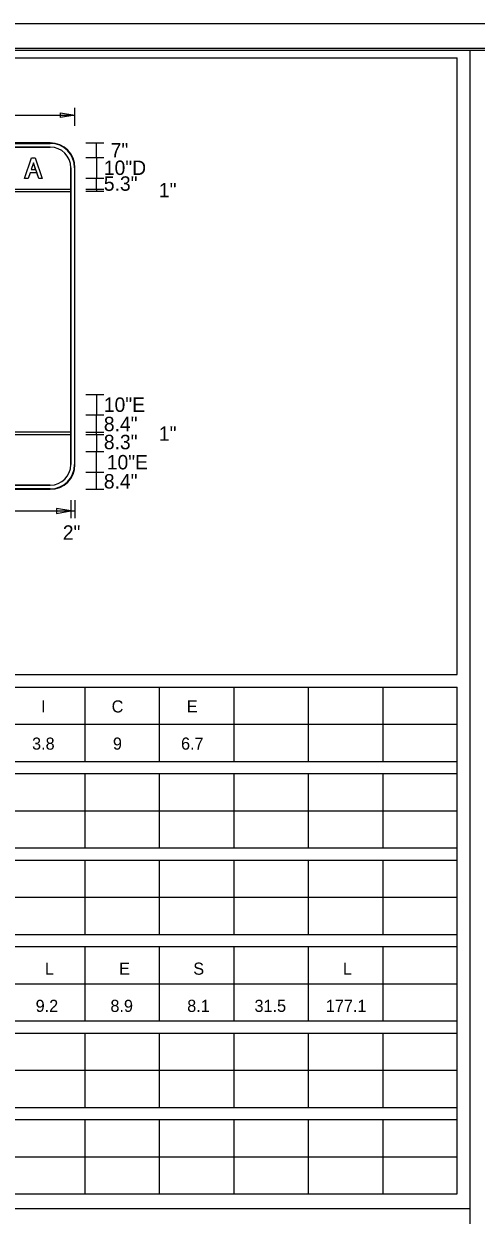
# Model space of a CAD drawing. Extents: x 17890071 to 17890754, y 17897628 to 17897992.
# Drawn here: x 17890133.85 to 17890152.13, y 17897822.34 to 17897870.5 of the extents above; entities that cross this region are included whole.
import ezdxf

# ---------------------------------------------------------------- set-up
doc = ezdxf.new("R2010")
doc.units = 0
for name, color, linetype in [('GSBWFill', 7, 'Continuous'), ('GSColorFill', 7, 'Continuous'), ('GSDims', 7, 'Continuous'), ('GSOutline', 7, 'Continuous'), ('GSSign', 7, 'Continuous'), ('PlotBorder_dp', 7, 'Continuous'), ('SheetBorder_dp', 7, 'Continuous'), ('SheetLinesMisc2_dp', 7, 'Continuous')]:
    doc.layers.add(name, color=color, linetype=linetype)

msp = doc.modelspace()

# ---------------------------------------------------------------- linework, layer by layer
at = {"layer": 'GSBWFill'}
for p, q in [((17890134.913, 17897865.68), (17890116.913, 17897865.68)), ((17890116.913, 17897865.514), (17890134.913, 17897865.514)), ((17890135.747, 17897864.68), (17890135.747, 17897852.68)), ((17890135.913, 17897852.68), (17890135.913, 17897864.68)), ((17890135.747, 17897863.798), (17890116.08, 17897863.798)), ((17890116.08, 17897863.715), (17890135.747, 17897863.715)), ((17890135.747, 17897863.715), (17890135.747, 17897863.798)), ((17890135.747, 17897853.984), (17890116.08, 17897853.984)), ((17890116.08, 17897853.901), (17890135.747, 17897853.901)), ((17890135.747, 17897853.901), (17890135.747, 17897853.984)), ((17890134.913, 17897851.847), (17890116.915, 17897851.847)), ((17890116.915, 17897851.68), (17890134.913, 17897851.68))]:
    msp.add_line(p, q, dxfattribs=at)
msp.add_lwpolyline([(17890133.88, 17897864.246), (17890134.163, 17897865.079), (17890134.305, 17897865.079), (17890134.588, 17897864.246), (17890134.447, 17897864.246), (17890134.234, 17897864.873), (17890134.144, 17897864.608), (17890134.324, 17897864.608), (17890134.369, 17897864.475), (17890134.099, 17897864.475), (17890134.021, 17897864.246)], close=True, dxfattribs=at)
for centre, radius, start, end in [((17890134.913, 17897864.68), 1, 0, 90), ((17890134.913, 17897864.68), 0.833, 0, 90), ((17890134.913, 17897852.68), 1, 270, 0), ((17890134.913, 17897852.68), 0.833, 270, 0)]:
    msp.add_arc(centre, radius, start, end, dxfattribs=at)
at = {"layer": 'GSColorFill'}
for p, q in [((17890134.913, 17897865.68), (17890116.913, 17897865.68)), ((17890134.913, 17897865.68), (17890116.913, 17897865.68)), ((17890134.913, 17897865.68), (17890116.913, 17897865.68)), ((17890116.913, 17897865.664), (17890134.913, 17897865.664)), ((17890116.913, 17897865.514), (17890134.913, 17897865.514)), ((17890135.747, 17897864.68), (17890135.747, 17897852.68)), ((17890135.897, 17897864.68), (17890135.897, 17897852.68)), ((17890135.913, 17897852.68), (17890135.913, 17897864.68)), ((17890135.913, 17897852.68), (17890135.913, 17897864.68)), ((17890135.913, 17897852.68), (17890135.913, 17897864.68)), ((17890135.747, 17897863.798), (17890116.08, 17897863.798)), ((17890116.08, 17897863.715), (17890135.747, 17897863.715)), ((17890135.747, 17897863.715), (17890135.747, 17897863.798)), ((17890135.747, 17897853.984), (17890116.08, 17897853.984)), ((17890116.08, 17897853.901), (17890135.747, 17897853.901)), ((17890135.747, 17897853.901), (17890135.747, 17897853.984)), ((17890134.913, 17897851.697), (17890116.913, 17897851.697)), ((17890116.913, 17897851.68), (17890134.913, 17897851.68)), ((17890116.913, 17897851.68), (17890134.913, 17897851.68)), ((17890134.913, 17897851.847), (17890116.915, 17897851.847)), ((17890116.915, 17897851.68), (17890134.913, 17897851.68))]:
    msp.add_line(p, q, dxfattribs=at)
msp.add_lwpolyline([(17890133.88, 17897864.246), (17890134.163, 17897865.079), (17890134.305, 17897865.079), (17890134.588, 17897864.246), (17890134.447, 17897864.246), (17890134.234, 17897864.873), (17890134.144, 17897864.608), (17890134.324, 17897864.608), (17890134.369, 17897864.475), (17890134.099, 17897864.475), (17890134.021, 17897864.246)], close=True, dxfattribs=at)
for centre, radius, start, end in [((17890134.913, 17897864.68), 1, 0, 90), ((17890134.913, 17897864.68), 1, 0, 90), ((17890134.913, 17897864.68), 1, 0, 90), ((17890134.913, 17897864.68), 0.983, 0, 90), ((17890134.913, 17897864.68), 0.833, 0, 90), ((17890134.913, 17897852.68), 1, 270, 0), ((17890134.913, 17897852.68), 1, 270, 0), ((17890134.913, 17897852.68), 0.833, 270, 0), ((17890134.913, 17897852.68), 1, 270, 0), ((17890134.913, 17897852.68), 0.983, 270, 0)]:
    msp.add_arc(centre, radius, start, end, dxfattribs=at)
at = {"layer": 'GSDims'}
for p, q in [((17890135.913, 17897866.368), (17890135.913, 17897867.097)), ((17890115.913, 17897866.806), (17890135.913, 17897866.806)), ((17890136.351, 17897865.68), (17890137.08, 17897865.68)), ((17890136.788, 17897865.094), (17890136.788, 17897865.68)), ((17890136.351, 17897865.094), (17890137.08, 17897865.094)), ((17890136.351, 17897865.094), (17890137.08, 17897865.094)), ((17890136.788, 17897865.094), (17890136.788, 17897864.26)), ((17890136.351, 17897864.26), (17890137.08, 17897864.26)), ((17890136.351, 17897864.26), (17890137.08, 17897864.26)), ((17890136.788, 17897863.815), (17890136.788, 17897864.26)), ((17890136.351, 17897863.815), (17890137.08, 17897863.815)), ((17890136.351, 17897863.815), (17890137.08, 17897863.815)), ((17890136.351, 17897863.732), (17890137.08, 17897863.732)), ((17890136.351, 17897863.732), (17890137.08, 17897863.732)), ((17890136.788, 17897863.815), (17890136.788, 17897863.732)), ((17890136.351, 17897855.517), (17890137.08, 17897855.517)), ((17890136.351, 17897855.517), (17890137.08, 17897855.517)), ((17890136.788, 17897855.517), (17890136.788, 17897854.684)), ((17890136.351, 17897854.684), (17890137.08, 17897854.684)), ((17890136.351, 17897854.684), (17890137.08, 17897854.684)), ((17890136.788, 17897853.984), (17890136.788, 17897854.684)), ((17890136.351, 17897853.984), (17890137.08, 17897853.984)), ((17890136.351, 17897853.984), (17890137.08, 17897853.984)), ((17890136.351, 17897853.9), (17890137.08, 17897853.9)), ((17890136.351, 17897853.9), (17890137.08, 17897853.9)), ((17890136.788, 17897853.9), (17890136.788, 17897853.984)), ((17890136.788, 17897853.9), (17890136.788, 17897853.213)), ((17890136.351, 17897853.213), (17890137.08, 17897853.213)), ((17890136.788, 17897852.379), (17890136.788, 17897853.213)), ((17890136.351, 17897852.379), (17890137.08, 17897852.379)), ((17890136.788, 17897851.68), (17890136.788, 17897852.379)), ((17890136.351, 17897851.68), (17890137.08, 17897851.68)), ((17890135.747, 17897851.243), (17890135.747, 17897850.514)), ((17890135.747, 17897851.243), (17890135.747, 17897850.514)), ((17890135.913, 17897851.243), (17890135.913, 17897850.514)), ((17890116.08, 17897850.805), (17890135.747, 17897850.805)), ((17890135.747, 17897850.805), (17890135.913, 17897850.805))]:
    msp.add_line(p, q, dxfattribs=at)
for points in [[(17890135.913, 17897866.806), (17890135.33, 17897866.708), (17890135.33, 17897866.903)], [(17890135.747, 17897850.805), (17890135.163, 17897850.903), (17890135.163, 17897850.708)]]:
    msp.add_lwpolyline(points, close=True, dxfattribs=at)
at = {"layer": 'GSOutline'}
for p, q in [((17890134.913, 17897865.68), (17890116.913, 17897865.68)), ((17890134.913, 17897865.514), (17890116.913, 17897865.514)), ((17890135.747, 17897852.68), (17890135.747, 17897864.68)), ((17890135.913, 17897852.68), (17890135.913, 17897864.68)), ((17890135.747, 17897863.798), (17890116.08, 17897863.798)), ((17890116.08, 17897863.715), (17890135.747, 17897863.715)), ((17890135.747, 17897863.715), (17890135.747, 17897863.798)), ((17890135.747, 17897853.984), (17890116.08, 17897853.984)), ((17890116.08, 17897853.901), (17890135.747, 17897853.901)), ((17890135.747, 17897853.901), (17890135.747, 17897853.984)), ((17890116.913, 17897851.847), (17890134.913, 17897851.847)), ((17890116.913, 17897851.68), (17890134.913, 17897851.68))]:
    msp.add_line(p, q, dxfattribs=at)
for points in [[(17890134.099, 17897864.475), (17890134.021, 17897864.246), (17890133.88, 17897864.246), (17890134.163, 17897865.079), (17890134.305, 17897865.079), (17890134.588, 17897864.246), (17890134.447, 17897864.246), (17890134.369, 17897864.475)], [(17890134.144, 17897864.608), (17890134.324, 17897864.608), (17890134.234, 17897864.873)]]:
    msp.add_lwpolyline(points, close=True, dxfattribs=at)
for centre, radius, start, end in [((17890134.913, 17897864.68), 1, 0, 90), ((17890134.913, 17897864.68), 0.833, 0, 90), ((17890134.913, 17897852.68), 1, 270, 0), ((17890134.913, 17897852.68), 0.833, 270, 0)]:
    msp.add_arc(centre, radius, start, end, dxfattribs=at)
at = {"layer": 'PlotBorder_dp'}
msp.add_lwpolyline([(17890071.13, 17897766.734), (17890232.646, 17897766.734), (17890232.646, 17897870.495), (17890071.13, 17897870.495)], close=True, dxfattribs=at)
at = {"layer": 'SheetBorder_dp'}
msp.add_line((17890076.514, 17897869.516), (17890227.262, 17897869.516), dxfattribs=at)
at = {"layer": 'SheetLinesMisc2_dp'}
for p, q in [((17890076.643, 17897869.435), (17890227.099, 17897869.435)), ((17890151.871, 17897869.435), (17890151.871, 17897775.777)), ((17890100.188, 17897869.124), (17890151.359, 17897869.124)), ((17890151.359, 17897844.198), (17890151.359, 17897869.124)), ((17890100.188, 17897844.198), (17890151.359, 17897844.198)), ((17890077.364, 17897843.684), (17890151.359, 17897843.684)), ((17890136.309, 17897843.684), (17890136.309, 17897840.678)), ((17890139.319, 17897843.684), (17890139.319, 17897840.678)), ((17890142.329, 17897843.684), (17890142.329, 17897840.678)), ((17890145.339, 17897843.684), (17890145.339, 17897840.678)), ((17890148.35, 17897843.684), (17890148.35, 17897840.678)), ((17890151.359, 17897823.197), (17890151.359, 17897843.684)), ((17890077.364, 17897842.181), (17890151.359, 17897842.181)), ((17890077.364, 17897840.678), (17890151.359, 17897840.678)), ((17890077.364, 17897840.188), (17890151.359, 17897840.188)), ((17890136.309, 17897840.188), (17890136.309, 17897837.182)), ((17890139.319, 17897840.188), (17890139.319, 17897837.182)), ((17890142.329, 17897840.188), (17890142.329, 17897837.182)), ((17890145.339, 17897840.188), (17890145.339, 17897837.182)), ((17890148.35, 17897840.188), (17890148.35, 17897837.182)), ((17890077.364, 17897838.684), (17890151.359, 17897838.685)), ((17890077.364, 17897837.182), (17890151.359, 17897837.182)), ((17890077.364, 17897836.692), (17890151.359, 17897836.692)), ((17890136.309, 17897836.692), (17890136.309, 17897833.686)), ((17890139.319, 17897836.692), (17890139.319, 17897833.686)), ((17890142.329, 17897836.692), (17890142.329, 17897833.686)), ((17890145.339, 17897836.692), (17890145.339, 17897833.686)), ((17890148.35, 17897836.692), (17890148.35, 17897833.686)), ((17890077.364, 17897835.188), (17890151.359, 17897835.188)), ((17890077.364, 17897833.686), (17890151.359, 17897833.686)), ((17890077.364, 17897833.195), (17890151.359, 17897833.195)), ((17890136.309, 17897833.195), (17890136.309, 17897830.189)), ((17890139.319, 17897833.195), (17890139.319, 17897830.189)), ((17890142.329, 17897833.195), (17890142.329, 17897830.189)), ((17890145.339, 17897833.195), (17890145.339, 17897830.189)), ((17890148.35, 17897833.195), (17890148.35, 17897830.189)), ((17890077.364, 17897831.692), (17890151.359, 17897831.692)), ((17890077.364, 17897830.189), (17890151.359, 17897830.189)), ((17890077.364, 17897829.699), (17890151.359, 17897829.699)), ((17890136.309, 17897829.699), (17890136.309, 17897826.693)), ((17890139.319, 17897829.699), (17890139.319, 17897826.693)), ((17890142.329, 17897829.699), (17890142.329, 17897826.693)), ((17890145.339, 17897829.699), (17890145.339, 17897826.693)), ((17890148.35, 17897829.699), (17890148.35, 17897826.693)), ((17890077.364, 17897828.196), (17890151.359, 17897828.196)), ((17890077.364, 17897826.693), (17890151.359, 17897826.693)), ((17890077.364, 17897826.202), (17890151.359, 17897826.202)), ((17890136.309, 17897826.202), (17890136.309, 17897823.197)), ((17890139.319, 17897826.202), (17890139.319, 17897823.197)), ((17890142.329, 17897826.202), (17890142.329, 17897823.197)), ((17890145.339, 17897826.202), (17890145.339, 17897823.197)), ((17890148.35, 17897826.202), (17890148.35, 17897823.197)), ((17890077.364, 17897824.7), (17890151.359, 17897824.7)), ((17890077.364, 17897823.197), (17890151.359, 17897823.197)), ((17890076.643, 17897822.606), (17890151.871, 17897822.606))]:
    msp.add_line(p, q, dxfattribs=at)

# ---------------------------------------------------------------- texts
at = {"layer": 'GSDims'}
for s, p in [('7"', (17890137.357, 17897865.095)), ('10"D', (17890137.08, 17897864.385)), ('5.3"', (17890137.08, 17897863.746)), ('1"', (17890139.306, 17897863.482)), ('10"E', (17890137.08, 17897854.809)), ('8.4"', (17890137.08, 17897854.029)), ('1"', (17890139.306, 17897853.64)), ('8.3"', (17890137.08, 17897853.299)), ('10"E', (17890137.199, 17897852.484)), ('8.4"', (17890137.08, 17897851.712)), ('2"', (17890135.421, 17897849.639))]:
    msp.add_text(s, height=0.5833, dxfattribs=at).set_placement(p)
at = {"layer": 'GSSign'}
for s, height, p in [('I', 0.49, (17890134.545, 17897842.658)), ('C', 0.49, (17890137.396, 17897842.658)), ('E', 0.49, (17890140.434, 17897842.658)), ('3.8', 0.4902, (17890134.18, 17897841.155)), ('9', 0.49, (17890137.447, 17897841.155)), ('6.7', 0.4902, (17890140.2, 17897841.155)), ('L', 0.49, (17890134.698, 17897832.058)), ('E', 0.49, (17890137.696, 17897832.058)), ('S', 0.49, (17890140.695, 17897832.058)), ('L', 0.49, (17890146.739, 17897832.058)), ('9.2', 0.4902, (17890134.324, 17897830.555)), ('8.9', 0.4902, (17890137.346, 17897830.555)), ('8.1', 0.4902, (17890140.45, 17897830.555)), ('31.5', 0.4902, (17890143.169, 17897830.555)), ('177.1', 0.4902, (17890146.051, 17897830.555))]:
    msp.add_text(s, height=height, dxfattribs=at).set_placement(p)

doc.saveas('drawing.dxf')
